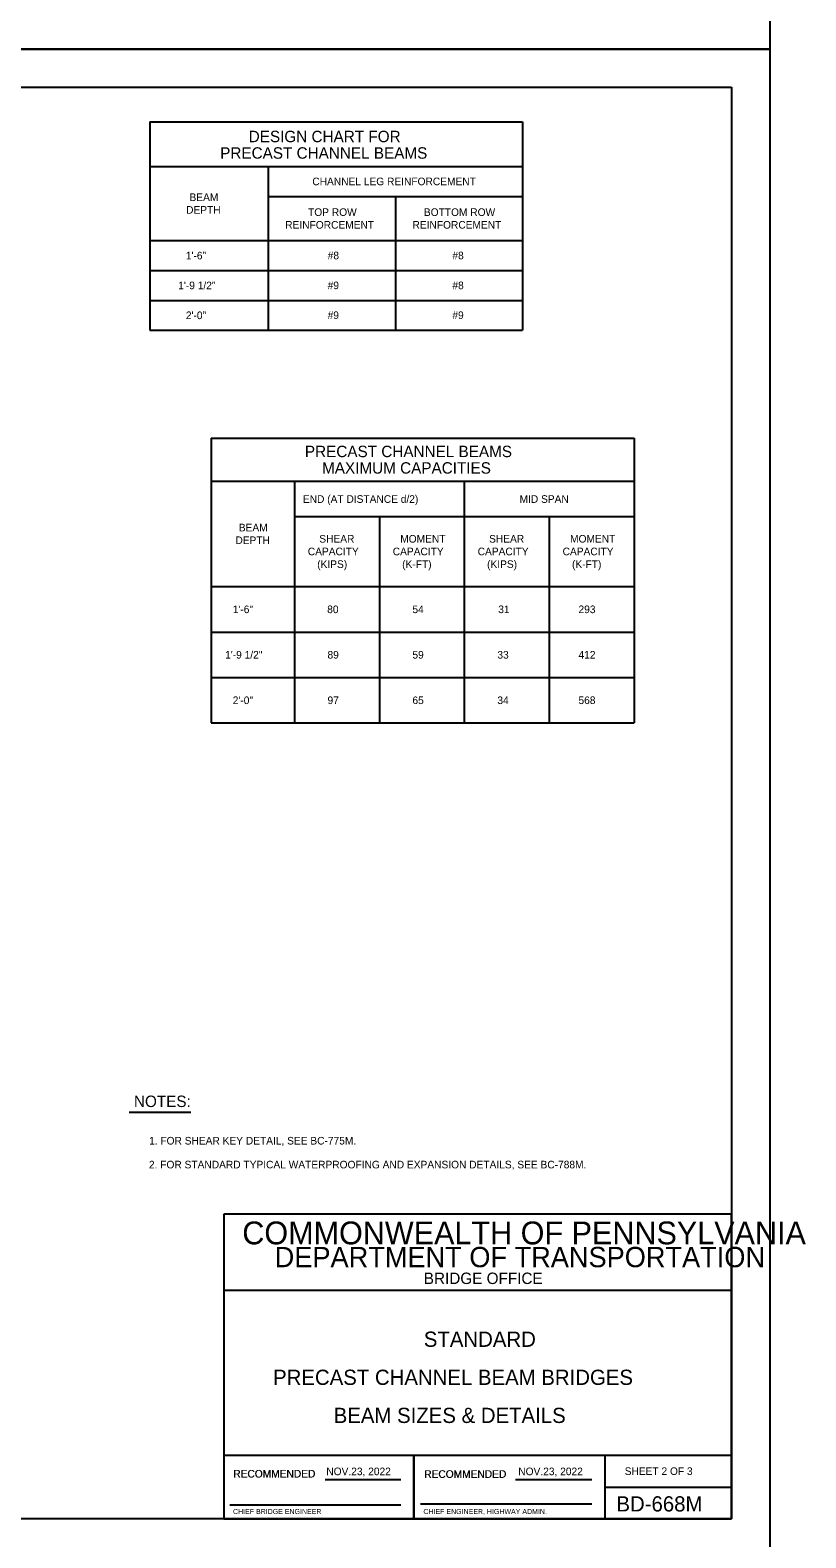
# Model space of a CAD drawing. Extents: x 642009 to 642864, y 298232 to 300014.
# Drawn here: x 642558 to 642864, y 298833 to 299427 of the extents above; entities that cross this region are included whole.
import ezdxf

# ---------------------------------------------------------------- set-up
doc = ezdxf.new("R2010")
doc.units = 0
for name, color, linetype in [('1', 7, 'Continuous'), ('2', 7, 'Continuous'), ('DATES', 7, 'Continuous'), ('PLT-BNDY', 7, 'Continuous'), ('SIGNATORY TITLES', 7, 'Continuous')]:
    doc.layers.add(name, color=color, linetype=linetype)

msp = doc.modelspace()

# ---------------------------------------------------------------- linework, layer by layer
at = {"layer": '1'}
for p, q in [((642629.65, 299266.58), (642796.25, 299266.58)), ((642629.65, 299249.59), (642796.25, 299249.59)), ((642729.34, 299249.59), (642729.34, 299154.36)), ((642662.43, 299235.76), (642796.25, 299235.76)), ((642695.89, 299235.76), (642695.89, 299154.36)), ((642762.79, 299235.76), (642762.79, 299154.36)), ((642629.65, 299208.1), (642796.25, 299208.1)), ((642629.65, 299190.18), (642796.25, 299190.18)), ((642629.65, 299172.27), (642796.25, 299172.27)), ((642629.65, 299154.36), (642796.25, 299154.36))]:
    msp.add_line(p, q, dxfattribs=at)
at = {"layer": '2'}
for p, q in [((642048.66, 299404.82), (642834.66, 299404.82)), ((642834.66, 299404.82), (642834.66, 298840.82)), ((642605.46, 299391.26), (642752.33, 299391.26)), ((642605.46, 299391.26), (642605.46, 299309.1)), ((642752.33, 299391.26), (642752.33, 299309.1)), ((642605.46, 299373.61), (642752.33, 299373.61)), ((642652.06, 299373.61), (642652.06, 299309.1)), ((642652.06, 299361.84), (642752.33, 299361.84)), ((642702.19, 299361.84), (642702.19, 299309.1)), ((642605.46, 299344.39), (642752.33, 299344.39)), ((642605.46, 299332.63), (642752.33, 299332.63)), ((642605.46, 299320.87), (642752.33, 299320.87)), ((642605.46, 299309.1), (642752.33, 299309.1)), ((642629.65, 299266.58), (642629.65, 299154.36)), ((642796.25, 299266.58), (642796.25, 299154.36)), ((642662.43, 299249.59), (642662.43, 299154.36)), ((642597.3, 299001.06), (642621.68, 299001.06)), ((642834.66, 298960.82), (642634.66, 298960.82)), ((642634.66, 298960.82), (642634.66, 298840.82)), ((642834.66, 298960.82), (642634.66, 298960.82)), ((642634.66, 298960.82), (642634.66, 298840.82)), ((642834.66, 298960.82), (642634.66, 298960.82)), ((642634.66, 298960.82), (642634.66, 298840.82)), ((642834.66, 298840.82), (642834.66, 298960.82)), ((642834.66, 298840.82), (642834.66, 298960.82)), ((642834.66, 298840.82), (642834.66, 298960.82)), ((642834.66, 298930.82), (642634.66, 298930.82)), ((642834.66, 298930.82), (642634.66, 298930.82)), ((642834.66, 298930.82), (642634.66, 298930.82)), ((642834.66, 298865.82), (642634.66, 298865.82)), ((642834.66, 298865.82), (642634.66, 298865.82)), ((642834.66, 298865.82), (642634.66, 298865.82)), ((642709.53, 298840.82), (642709.53, 298865.82)), ((642709.66, 298840.82), (642709.66, 298865.82)), ((642784.66, 298865.82), (642784.66, 298840.82)), ((642784.66, 298865.82), (642784.66, 298840.82)), ((642784.66, 298865.76), (642784.66, 298840.82)), ((642674.5, 298856.32), (642704.26, 298856.32)), ((642674.62, 298856.32), (642704.39, 298856.32)), ((642749.5, 298856.32), (642779.41, 298856.32)), ((642749.62, 298856.32), (642779.53, 298856.32)), ((642784.66, 298853.32), (642834.66, 298853.32)), ((642784.66, 298853.32), (642834.66, 298853.32)), ((642784.66, 298853.32), (642834.66, 298853.32)), ((642637.03, 298846.32), (642704.26, 298846.32)), ((642637.16, 298846.32), (642704.39, 298846.32)), ((642712.16, 298846.7), (642779.41, 298846.7)), ((642712.28, 298846.7), (642779.53, 298846.7)), ((642834.66, 298840.82), (642048.66, 298840.82)), ((642634.66, 298840.82), (642834.66, 298840.82)), ((642634.66, 298840.82), (642834.66, 298840.82)), ((642635.03, 298840.82), (642784.66, 298840.82))]:
    msp.add_line(p, q, dxfattribs=at)
at = {"layer": 'PLT-BNDY'}
for points in [[(642008.66, 300013.82), (642849.66, 300013.82), (642849.66, 299419.82), (642008.66, 299419.82)], [(642008.66, 299419.82), (642849.66, 299419.82), (642849.66, 298825.82), (642008.66, 298825.82)]]:
    msp.add_lwpolyline(points, close=True, dxfattribs=at)

# ---------------------------------------------------------------- texts
at = {"layer": '1'}
for s, p in [('END (AT DISTANCE d/2)', (642665.77, 299241.09)), ('MID SPAN', (642751.12, 299241.09)), ('DEPTH', (642639.19, 299224.85)), ('BEAM', (642640.54, 299229.85)), ('SHEAR', (642672.23, 299225.43)), ('MOMENT', (642704.12, 299225.43)), ('SHEAR', (642739.13, 299225.43)), ('MOMENT', (642771.03, 299225.43)), ('CAPACITY', (642667.71, 299220.43)), ('CAPACITY', (642701.17, 299220.43)), ('CAPACITY', (642734.62, 299220.43)), ('CAPACITY', (642768.08, 299220.43)), ('(KIPS)', (642671.42, 299215.43)), ('(K-FT)', (642704.88, 299215.43)), ('(KIPS)', (642738.33, 299215.43)), ('(K-FT)', (642771.78, 299215.43)), ('1\'-6"', (642638.14, 299197.64)), ('1\'-9 1/2"', (642635.14, 299179.73)), ('2\'-0"', (642638.14, 299161.81))]:
    msp.add_text(s, height=3, dxfattribs=at).set_placement(p)
for s, p in [('80', (642675.35, 299197.64)), ('54', (642708.93, 299197.64)), ('31', (642742.73, 299197.64)), ('293', (642774.34, 299197.64)), ('89', (642675.47, 299179.73)), ('59', (642708.92, 299179.73)), ('33', (642742.39, 299179.73)), ('412', (642774.34, 299179.73)), ('97', (642675.48, 299161.81)), ('65', (642708.93, 299161.81)), ('34', (642742.39, 299161.81)), ('568', (642774.34, 299161.81))]:
    msp.add_text(s, height=3, rotation=360, dxfattribs=at).set_placement(p)
at = {"layer": '2'}
for s, height, p in [('DESIGN CHART FOR', 4.5, (642644.43, 299383.18)), ('PRECAST CHANNEL BEAMS', 4.5, (642633.2, 299376.68)), ('RECOMMENDED', 3, (642638.3, 298857.07)), ('RECOMMENDED', 3, (642638.43, 298857.07)), ('RECOMMENDED', 3, (642713.52, 298856.95)), ('RECOMMENDED', 3, (642713.65, 298856.95))]:
    msp.add_text(s, height=height, rotation=360, dxfattribs=at).set_placement(p)
for s, height, p in [('CHANNEL LEG REINFORCEMENT', 3, (642669.49, 299366.22)), ('BEAM', 3, (642621.11, 299360)), ('DEPTH', 3, (642619.78, 299355)), ('TOP ROW', 3, (642667.81, 299354.12)), ('BOTTOM ROW', 3, (642713.44, 299354.12)), ('REINFORCEMENT', 3, (642658.82, 299349.12)), ('REINFORCEMENT', 3, (642708.95, 299349.12)), ('1\'-6"', 3, (642619.67, 299337.01)), ('#8', 3, (642675.55, 299337.04)), ('#8', 3, (642724.67, 299337.04)), ('1\'-9 1/2"', 3, (642616.67, 299325.25)), ('#9', 3, (642675.53, 299325.27)), ('#8', 3, (642724.67, 299325.27)), ('2\'-0"', 3, (642619.67, 299313.48)), ('#9', 3, (642675.53, 299313.51)), ('#9', 3, (642724.66, 299313.51)), ('PRECAST CHANNEL BEAMS', 4.5, (642666.57, 299259.09)), ('MAXIMUM CAPACITIES', 4.5, (642673.32, 299252.59)), ('NOTES:', 4.5, (642599.22, 299003.05)), ('1. FOR SHEAR KEY DETAIL, SEE BC-775M.', 3, (642605.18, 298988.28)), ('2. FOR STANDARD TYPICAL WATERPROOFING AND EXPANSION DETAILS, SEE BC-788M.', 3, (642605.13, 298978.88)), ('COMMONWEALTH OF PENNSYLVANIA', 9, (642641.91, 298948.95)), ('DEPARTMENT OF TRANSPORTATION', 8.0002, (642654.66, 298939.95)), ('BRIDGE OFFICE', 4.5, (642713.41, 298933.32)), ('STANDARD', 6, (642713.41, 298908.57)), ('PRECAST CHANNEL BEAM BRIDGES', 6, (642654.03, 298893.57)), ('BEAM SIZES & DETAILS', 6, (642677.91, 298878.57)), ('SHEET 2 OF 3', 3, (642792.54, 298858.09)), ('BD-668M', 6, (642789.28, 298843.7)), ('CHIEF BRIDGE ENGINEER', 2.0002, (642638.25, 298842.7))]:
    msp.add_text(s, height=height, dxfattribs=at).set_placement(p)
at = {"layer": 'DATES'}
for p in [(642675, 298858), (642750.62, 298858)]:
    msp.add_text('NOV.23, 2022', height=3, dxfattribs=at).set_placement(p)
at = {"layer": 'SIGNATORY TITLES'}
for s, p in [('CHIEF BRIDGE ENGINEER', (642638.25, 298842.7)), ('CHIEF ENGINEER, HIGHWAY ADMIN.', (642713.25, 298842.7))]:
    msp.add_text(s, height=2, dxfattribs=at).set_placement(p)

doc.saveas('drawing.dxf')
